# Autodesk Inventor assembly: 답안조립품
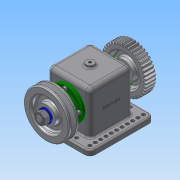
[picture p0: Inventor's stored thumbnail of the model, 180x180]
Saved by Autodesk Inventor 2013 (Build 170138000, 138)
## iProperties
Created: 2018-11
Part Number: 답안조립품
Document SubType Name: Assembly
Designer: kg
Author: kg
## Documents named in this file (13)
- C:\Users\kg\Desktop\481107V1011\답안조립품.iam
- C:\Users\kg\Desktop\481107V1011\본체.ipt
- C:\Users\kg\Desktop\481107V1011\V벨트풀리.ipt
- C:\Users\kg\Desktop\481107V1011\너트 M12x1.25.ipt
- C:\Users\kg\Desktop\481107V1011\베어링 6203.ipt
- C:\Users\kg\Desktop\481107V1011\볼트 M4.ipt
- C:\Users\kg\Desktop\481107V1011\부시.ipt
- C:\Users\kg\Desktop\481107V1011\스퍼기어.ipt
- C:\Users\kg\Desktop\481107V1011\오일 실 26 38 8.ipt
- C:\Users\kg\Desktop\481107V1011\와셔 12x24.ipt
- C:\Users\kg\Desktop\481107V1011\축.ipt
- C:\Users\kg\Desktop\481107V1011\커버.ipt
- C:\Users\kg\Desktop\481107V1011\키 5x5x12.ipt
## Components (1 placed, 1 different names)
1. V벨트풀리:1
